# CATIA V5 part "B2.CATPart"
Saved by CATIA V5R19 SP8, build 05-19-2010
Part number: B2
Publications: "Li", "La", "e", "r"
Bounding box of the stored display mesh (mm): x -15 to 165, y -15 to 15, z -14.942 to 14.942
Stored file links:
  C:\Users\ThinkMotion\Desktop\EU_thinkMotion\iao\IAO_MMS_Groupe3\evulliez\evulliez\evulliez\Mecanisme\B2.CATPart
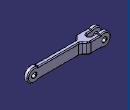
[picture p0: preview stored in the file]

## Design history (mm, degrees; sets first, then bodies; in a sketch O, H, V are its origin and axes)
Parameters
  Li = 150 mm
  La = 25 mm
  e = 10 mm
  r = 5 mm
Body1 (main body)
  Point1: (0, 0, 0)
  Line1: type PtDir, RefPoint Point1, Direction (1, 0, 0), Start 0, End 150 {= Li}
  Line2: type PtDir, RefPoint Point1, Direction (0, 1, 0), Start -15, End 15 {= (3*e )/2}
  Line3: type PtDir, RefPoint vertex of Line1, Direction (0, 1, 0), Start -5, End 5 {= e /2}
  Sketch1 on zx-plane, origin (0, 0, 0), H (-1, 0, 0), V (0, 0, 1)
    line L1 (-141.7084, 12.5) -> (-8.2916, 12.5)
    point P1 (-141.7084, 12.5)
    point P2 (-8.2916, 12.5)
    arc A1 centre (0, 0) radius 15 from (-8.2916, -12.5) to (-8.2916, 12.5) ccw
    point P3 (0, 0)
    point P4 (-8.2916, -12.5)
    point P5 (-8.2916, 12.5)
    reference projected point E1 (0, 0) from Point1
    reference projected point E2 (15, 0) from vertex [element of Sketch2 | element of Sketch2]
    arc A2 centre (-150, 0) radius 15 from (-141.7084, 12.5) to (-141.7084, -12.5) ccw
    point P6 (-150, 0)
    point P7 (-141.7084, 12.5)
    reference projected point E3 (-150, 0) from vertex of Line1
    reference projected point E4 (-165, 0) from vertex [element of Sketch2 | element of Sketch2]
    line L2 (-141.7084, -12.5) -> (-8.2916, -12.5)
    point P9 (-8.2916, -12.5)
    reference projected line E5 (0, 0) -> (-150, 0) from Line1
    distance E5 L1 = 12.5 {= La /2}
    distance L2 L1 = 25 {= La}
    horizontal: L1 H, L2 H
    coincidence: E1 P3, A1 E2, P2 P5, P6 E3, E4 A2, P7 P1, P4 P9
  Sketch2 on xy-plane, origin (0, 0, 0), H (1, 0, 0), V (0, 1, 0)
    line L1 (-15, -15) -> (35, -15)
    point P2 (35, -15)
    line L2 (-15, -15) -> (-15, -5)
    line L3 (-15, -5) -> (20, -5)
    point P4 (20, -5)
    point P5 (20, 5)
    line L4 (20, 5) -> (-15, 5)
    point P6 (-15, 5)
    line L5 (-15, 5) -> (-15, 15)
    line L6 (-15, 15) -> (35, 15)
    point P8 (35, 15)
    point P9 (45, 5)
    line L7 (45, 5) -> (165, 5)
    line L8 (165, 5) -> (165, -5)
    line L9 (165, -5) -> (45, -5)
    point P12 (45, -5)
    reference projected point E1 (150, 5) from vertex of Line3
    reference projected point E2 (150, -5) from vertex of Line3
    reference projected line E3 (150, -5) -> (150, 5) from Line3
    reference projected line E4 (0, -15) -> (0, 15) from Line2
    reference projected point E5 (0, -15) from vertex of Line2
    reference projected point E6 (0, 15) from vertex of Line2
    line L10 (35, 15) -> (45, 5)
    line L11 (35, -15) -> (45, -5)
    reference projected line E7 (0, -15) -> (0, 15) from Line2
    reference projected line E8 (0, -15) -> (0, 15) from Line2
    reference projected line E9 (0, -15) -> (0, 15) from Line2
    reference projected line E10 (0, -15) -> (0, 15) from Line2
    reference projected line E11 (0, -15) -> (0, 15) from Line2
    reference projected line E12 (0, -15) -> (0, 15) from Line2
    arc A1 centre (20, 0) radius 5 from (20, -5) to (20, 5) ccw
    point P13 (20, 0)
    point P14 (20, -5)
    point P15 (20, 5)
    reference projected line E13 (0, 0) -> (150, 0) from Line1
    length L2 = 10 {= e}
    length L5 = 10 {= e}
    distance E3 L8 = 15 {= r +10mm}
    distance E4 L5 = 15 {= r +10mm}
    distance E7 P8 = 35 {= e +r +20mm}
    distance E8 P2 = 35 {= e +r +20mm}
    distance E9 P9 = 45 {= e +r +20mm+e}
    distance E10 P12 = 45 {= e +r +20mm+e}
    distance P5 E11 = 20 {= r +15mm}
    distance E12 P4 = 20 {= r +15mm}
    horizontal: L1 H, L3 H, L4 H, L6 H, L7 H, L9 H
    vertical: L2 V, L5 V, L8 V
    coincidence: P6 L2, E1 L7, E2 L9, E5 L1, E6 L6, P13 E13, P15 P5, P14 P4
  SolidCombine1: FirstComponentProfile Sketch1, FirstComponentDirection Sketch1, SecondComponentProfile Sketch2, SecondComponentDirection Sketch2
  Sketch3 on face of SolidCombine1 from Sketch2.L6, origin (0, 15, 0), H (1, 0, 0), V (0, 0, -1)
    point P1 (0, 0)
    reference projected point E1 (0, 0) from vertex of Line2
    coincidence: E1 P1
  Hole1: placed by Sketch3, at (0, 15, 0) direction (0, -1, 0), diameter 10 {= r *2}, through (limit type 3)
  Sketch4 on face of SolidCombine1 from Sketch2.L7, origin (150, 5, 0), H (1, 0, 0), V (0, 0, -1)
    point P1 (0, 0)
    reference projected point E1 (0, 0) from vertex of Line3
    coincidence: E1 P1
  Hole2: placed by Sketch4, at (150, 5, 0) direction (0, -1, 0), diameter 10 {= r *2}, through (limit type 3)
  Fillet1: radius 1, on edge [face of Hole1 | face of SolidCombine1 from Sketch2.L6]; edge [face of Hole2 | face of SolidCombine1 from Sketch2.L7]; edge [face of Hole2 | face of SolidCombine1 from Sketch2.L9]; edge [face of SolidCombine1 from Sketch2.L1 | face of Hole1]; edge [face of SolidCombine1 from Sketch2.L4 | face of Hole1]; edge [face of SolidCombine1 from Sketch2.L3 | face of Hole1]
  Fillet2: radius 2, on edge [face of SolidCombine1 from Sketch2.A1 | face of SolidCombine1 from Sketch1.L1]; edge [face of SolidCombine1 from Sketch1.L1 | face of SolidCombine1 from Sketch2.L3]; edge [face of SolidCombine1 from Sketch2.L4 | face of SolidCombine1 from Sketch1.L1]; edge [face of SolidCombine1 from Sketch1.A1 | face of SolidCombine1 from Sketch2.L4]; edge [face of SolidCombine1 from Sketch1.A1 | face of SolidCombine1 from Sketch2.L3]; edge [face of SolidCombine1 from Sketch1.A1 | face of SolidCombine1 from Sketch2.L1]; edge [face of SolidCombine1 from Sketch2.L1 | face of SolidCombine1 from Sketch1.L1]; edge [face of SolidCombine1 from Sketch2.L11 | face of SolidCombine1 from Sketch1.L1]; edge [face of SolidCombine1 from Sketch1.L2 | face of SolidCombine1 from Sketch2.L1]; edge [face of SolidCombine1 from Sketch1.L2 | face of SolidCombine1 from Sketch2.L11]; edge [face of SolidCombine1 from Sketch2.L9 | face of SolidCombine1 from Sketch1.L2]; edge [face of SolidCombine1 from Sketch1.L1 | face of SolidCombine1 from Sketch2.L9]; edge [face of SolidCombine1 from Sketch2.L9 | face of SolidCombine1 from Sketch1.A2]; edge [face of SolidCombine1 from Sketch2.L7 | face of SolidCombine1 from Sketch1.A2]; edge [face of SolidCombine1 from Sketch2.L7 | face of SolidCombine1 from Sketch1.L1]; edge [face of SolidCombine1 from Sketch1.L1 | face of SolidCombine1 from Sketch2.L10]; edge [face of SolidCombine1 from Sketch1.L1 | face of SolidCombine1 from Sketch2.L6]; edge [face of SolidCombine1 from Sketch2.L6 | face of SolidCombine1 from Sketch1.A1]; edge [face of SolidCombine1 from Sketch1.L2 | face of SolidCombine1 from Sketch2.L7]; edge [face of SolidCombine1 from Sketch2.L10 | face of SolidCombine1 from Sketch1.L2]; edge [face of SolidCombine1 from Sketch2.L6 | face of SolidCombine1 from Sketch1.L2]; edge [face of SolidCombine1 from Sketch1.L2 | face of SolidCombine1 from Sketch2.L4]; edge [face of SolidCombine1 from Sketch2.L3 | face of SolidCombine1 from Sketch1.L2]; edge [face of SolidCombine1 from Sketch1.L2 | face of SolidCombine1 from Sketch2.A1]
  Fillet3: radius 10, on edge [face of SolidCombine1 from Sketch2.L6 | face of SolidCombine1 from Sketch2.L10]; edge [face of SolidCombine1 from Sketch2.L10 | face of SolidCombine1 from Sketch2.L7]; edge [face of SolidCombine1 from Sketch2.L9 | face of SolidCombine1 from Sketch2.L11]; edge [face of SolidCombine1 from Sketch2.L11 | face of SolidCombine1 from Sketch2.L1]
  Fillet4: radius 5, on edge [face of SolidCombine1 from Sketch1.L1 | face of SolidCombine1 from Sketch1.A1] (x2); edge [face of SolidCombine1 from Sketch1.A2 | face of SolidCombine1 from Sketch1.L1]; edge [face of SolidCombine1 from Sketch1.L2 | face of SolidCombine1 from Sketch1.A2]; edge [face of SolidCombine1 from Sketch1.A1 | face of SolidCombine1 from Sketch1.L2] (x2)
